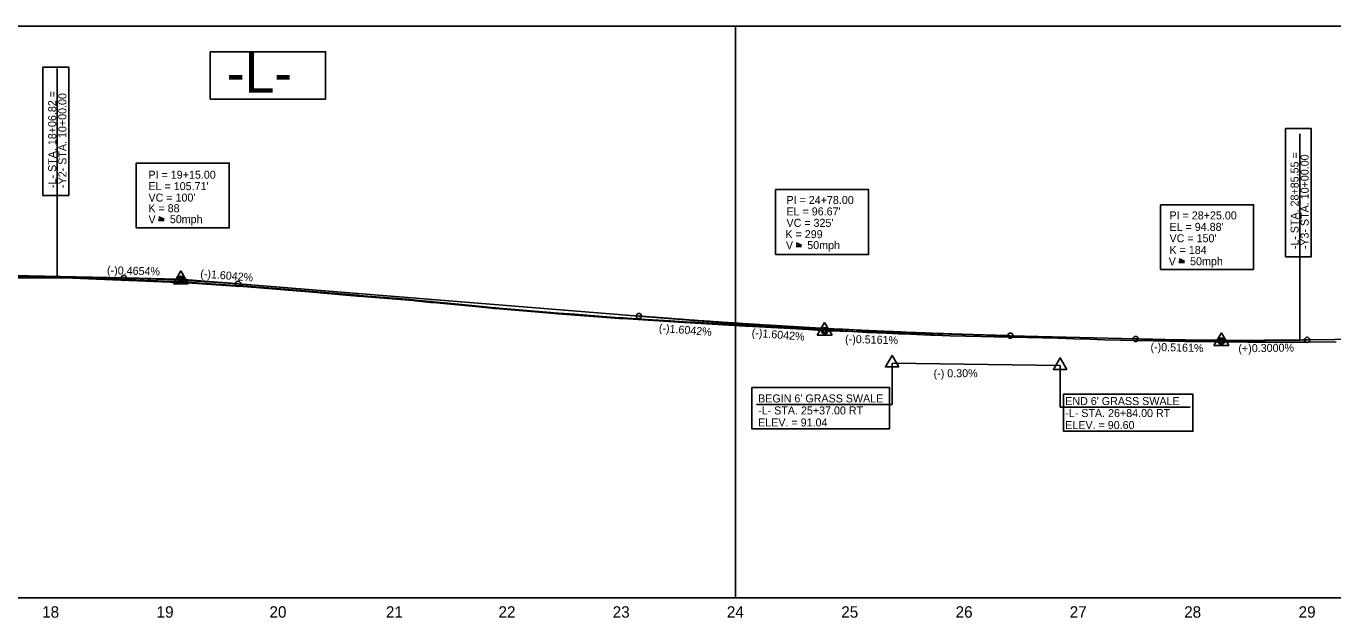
# Model space of a CAD drawing. Extents: x 2366464 to 2375718, y 801842 to 804354.
# Drawn here: x 2368098 to 2369240, y 803836 to 804354 of the extents above; entities that cross this region are included whole.
import ezdxf

# ---------------------------------------------------------------- set-up
doc = ezdxf.new("R2010")
doc.units = 0
for name, color, linetype in [('Exist Profile Cell', 7, 'Continuous'), ('Exist Vertical Profile Ground Line', 7, 'Continuous'), ('Exist Vertical Profile Horizontal Axis Label Major', 7, 'Continuous'), ('Prop Grid Mask', 7, 'Continuous'), ('Prop PFL VPI Symbol CELL', 7, 'Continuous'), ('Prop Vertical Profile Curve Label', 7, 'Continuous'), ('Prop Vertical Profile Ditch Grade Right', 7, 'Continuous'), ('Prop Vertical Profile Ditch Grade Right Label', 7, 'Continuous'), ('Prop Vertical Profile Grade', 7, 'Continuous'), ('Prop Vertical Profile Grade Label', 7, 'Continuous'), ('Prop VPI Label', 7, 'Continuous'), ('Scratch_Level_5', 7, 'Continuous'), ('Sheet Layout Profile Border Port 1', 7, 'Continuous'), ('Sheet Layout Profile Border Port 2', 7, 'Continuous')]:
    doc.layers.add(name, color=color, linetype=linetype)

# ---------------------------------------------------------------- blocks, each defined once
blk = doc.blocks.new('Profile VPI Symbol')
at = {"layer": 'Prop PFL VPI Symbol CELL'}
for p, q in [((-0.001, 0.147), (-0.13, -0.077)), ((-0.001, 0.147), (0.129, -0.077)), ((-0.13, -0.077), (0.129, -0.077))]:
    blk.add_line(p, q, dxfattribs=at)
for radius in [0.035, 0.024]:
    blk.add_circle((-0.001, -0.003), radius, dxfattribs=at)

msp = doc.modelspace()

# ---------------------------------------------------------------- linework, layer by layer
at = {"layer": 'Exist Profile Cell'}
msp.add_line((2367318, 803854), (2374481.8, 803854), dxfattribs=at)
at = {"layer": 'Exist Vertical Profile Ground Line'}
for points in [[(2368089.7, 804134.6), (2368138.2, 804134.2), (2368187.3, 804132.2), (2368187.8, 804132.2), (2368237.8, 804130), (2368238.2, 804130), (2368238.5, 804129.9), (2368280.6, 804127.2), (2368287.8, 804126.8), (2368337.8, 804122.6), (2368338.4, 804122.6), (2368387.6, 804118.5), (2368388.5, 804118.4), (2368430.6, 804115), (2368436.1, 804114.5), (2368438.1, 804114.3), (2368451.5, 804113), (2368452.1, 804113), (2368452.9, 804112.9), (2368453.8, 804112.8), (2368472.5, 804111), (2368493.5, 804108.9), (2368507.2, 804107.6), (2368507.6, 804107.5), (2368508.1, 804107.5), (2368514.5, 804107), (2368535.4, 804105.3), (2368556.4, 804103.5), (2368562.6, 804103), (2368563.1, 804103), (2368577.4, 804101.9), (2368598.4, 804100.3), (2368616.3, 804098.9), (2368618.5, 804098.8), (2368619.4, 804098.7), (2368640.3, 804097.4), (2368661.3, 804096.1), (2368672.8, 804095.4), (2368673.4, 804095.4), (2368682.3, 804094.9), (2368703.2, 804093.6), (2368724.2, 804092.4), (2368726.7, 804092.3), (2368727.3, 804092.2), (2368727.7, 804092.2), (2368745.2, 804091.2), (2368766.1, 804090), (2368781.9, 804089.1), (2368787.1, 804088.8)], [(2368787.1, 804088.8), (2368802.9, 804087.9), (2368808.1, 804087.6), (2368829.1, 804086.4), (2368832.6, 804086.2), (2368833, 804086.1), (2368850, 804085.4), (2368860.4, 804084.9), (2368871, 804084.5), (2368888.6, 804083.7), (2368889.1, 804083.7), (2368892, 804083.6), (2368905.6, 804083.2), (2368919.1, 804082.9), (2368932.7, 804082.5), (2368944.4, 804082.2), (2368944.9, 804082.2), (2368946.2, 804082.2), (2368959.8, 804081.8), (2368973.3, 804081.5), (2368986.9, 804081.2), (2368999.8, 804080.9), (2369000.5, 804080.9), (2369014, 804080.5), (2369027.6, 804080.1), (2369041.1, 804079.7), (2369054.7, 804079.3), (2369055.5, 804079.3), (2369068.2, 804079), (2369070.3, 804079), (2369111.4, 804078), (2369165.9, 804077.6), (2369203.5, 804077.6), (2369218.2, 804077.6), (2369218.7, 804077.6), (2369243.4, 804077.7)]]:
    msp.add_lwpolyline(points, dxfattribs=at)
at = {"layer": 'Prop Grid Mask'}
for points in [[(2368258.7, 804331.5), (2368359.5, 804331.5), (2368359.5, 804290.2), (2368258.7, 804290.2)], [(2368112.3, 804205.9), (2368112.3, 804318), (2368134.9, 804318), (2368134.9, 804205.9)], [(2369198.9, 804152.3), (2369198.9, 804264.4), (2369221.5, 804264.4), (2369221.5, 804152.3)], [(2368193.9, 804234.2), (2368275.2, 804234.2), (2368275.2, 804177.5), (2368193.9, 804177.5)], [(2368753.1, 804211), (2368834.4, 804211), (2368834.4, 804154.3), (2368753.1, 804154.3)], [(2369089.8, 804197.8), (2369171.2, 804197.8), (2369171.2, 804141.1), (2369089.8, 804141.1)], [(2368732.4, 804037.9), (2368852.7, 804037.9), (2368852.7, 804001.7), (2368732.4, 804001.7)], [(2369005, 804032), (2369118.1, 804032), (2369118.1, 803999.6), (2369005, 803999.6)]]:
    msp.add_lwpolyline(points, close=True, dxfattribs=at)
at = {"layer": 'Prop Vertical Profile Curve Label'}
for p, q in [((2368218.3, 804185.1), (2368213.6, 804187.1)), ((2368213.5, 804185.1), (2368218.3, 804185.1)), ((2368213.5, 804184), (2368218.3, 804184)), ((2368775.8, 804162.4), (2368771.2, 804164.4)), ((2368771.1, 804162.4), (2368775.8, 804162.4)), ((2368771.1, 804161.3), (2368775.8, 804161.3)), ((2369105.9, 804148.3), (2369110.6, 804148.3)), ((2369105.9, 804147.2), (2369110.6, 804147.2)), ((2369110.6, 804148.3), (2369106, 804150.3))]:
    msp.add_line(p, q, dxfattribs=at)
for centre in [(2368183, 804133.7), (2368283, 804128.5), (2368633.5, 804100.4), (2368958.5, 804083.2), (2369068, 804080.3), (2369218, 804079.5)]:
    msp.add_circle(centre, 2.25, dxfattribs=at)
at = {"layer": 'Prop Vertical Profile Ditch Grade Right'}
msp.add_line((2369002, 804057), (2368855, 804059.2), dxfattribs=at)
at = {"layer": 'Prop Vertical Profile Ditch Grade Right Label'}
for p, q in [((2368855, 804022.9), (2368855, 804059.2)), ((2369002, 804020.7), (2369002, 804057)), ((2368855, 804022.9), (2368736.5, 804022.9)), ((2369115.7, 804020.7), (2369002, 804020.7))]:
    msp.add_line(p, q, dxfattribs=at)
for points in [[(2368860.8, 804055.8), (2368855, 804065.9), (2368849.1, 804055.8)], [(2369007.8, 804053.6), (2369002, 804063.7), (2368996.1, 804053.6)]]:
    msp.add_lwpolyline(points, close=True, dxfattribs=at)
at = {"layer": 'Prop Vertical Profile Grade'}
for p, q in [((2367768, 804143.3), (2368183, 804133.7)), ((2368283, 804128.5), (2368633.5, 804100.4)), ((2368958.5, 804083.2), (2369068, 804080.3)), ((2369218, 804079.5), (2369269, 804080.3))]:
    msp.add_line(p, q, dxfattribs=at)
for points in [[(2368183, 804133.7), (2368185, 804133.6), (2368187, 804133.6), (2368189, 804133.5), (2368191, 804133.5), (2368193, 804133.4), (2368195, 804133.4), (2368197, 804133.3), (2368199, 804133.2), (2368201, 804133.2), (2368203, 804133.1), (2368205, 804133), (2368207, 804133), (2368209, 804132.9), (2368211, 804132.8), (2368213, 804132.7), (2368215, 804132.6), (2368217, 804132.6), (2368219, 804132.5), (2368221, 804132.4), (2368223, 804132.3), (2368225, 804132.2), (2368227, 804132.1), (2368229, 804132), (2368231, 804131.9), (2368233, 804131.8), (2368235, 804131.7), (2368237, 804131.6), (2368239, 804131.5), (2368241, 804131.4), (2368243, 804131.3), (2368245, 804131.1), (2368247, 804131), (2368249, 804130.9), (2368251, 804130.8), (2368253, 804130.7), (2368255, 804130.5), (2368257, 804130.4), (2368259, 804130.3), (2368261, 804130.1), (2368263, 804130), (2368265, 804129.9), (2368267, 804129.7), (2368269, 804129.6), (2368271, 804129.4), (2368273, 804129.3), (2368275, 804129.1), (2368277, 804129), (2368279, 804128.8), (2368281, 804128.7), (2368283, 804128.5)], [(2368633.5, 804100.4), (2368640, 804099.9), (2368646.5, 804099.4), (2368653, 804098.9), (2368659.5, 804098.4), (2368666, 804097.9), (2368672.5, 804097.4), (2368679, 804096.9), (2368685.5, 804096.4), (2368692, 804096), (2368698.5, 804095.5), (2368705, 804095.1), (2368711.5, 804094.6), (2368718, 804094.2), (2368724.5, 804093.8), (2368731, 804093.4), (2368737.5, 804093), (2368744, 804092.5), (2368750.5, 804092.2), (2368757, 804091.8), (2368763.5, 804091.4), (2368770, 804091), (2368776.5, 804090.6), (2368783, 804090.3), (2368789.5, 804089.9), (2368796, 804089.6), (2368802.5, 804089.2), (2368809, 804088.9), (2368815.5, 804088.6), (2368822, 804088.2), (2368828.5, 804087.9), (2368835, 804087.6), (2368841.5, 804087.3), (2368848, 804087), (2368854.5, 804086.8), (2368861, 804086.5), (2368867.5, 804086.2), (2368874, 804085.9), (2368880.5, 804085.7), (2368887, 804085.4), (2368893.5, 804085.2), (2368900, 804085), (2368906.5, 804084.7), (2368913, 804084.5), (2368919.5, 804084.3), (2368926, 804084.1), (2368932.5, 804083.9), (2368939, 804083.7), (2368945.5, 804083.5), (2368952, 804083.3), (2368958.5, 804083.2)], [(2369068, 804080.3), (2369071, 804080.3), (2369074, 804080.2), (2369077, 804080.1), (2369080, 804080), (2369083, 804080), (2369086, 804079.9), (2369089, 804079.9), (2369092, 804079.8), (2369095, 804079.7), (2369098, 804079.7), (2369101, 804079.6), (2369104, 804079.6), (2369107, 804079.5), (2369110, 804079.5), (2369113, 804079.4), (2369116, 804079.4), (2369119, 804079.4), (2369122, 804079.3), (2369125, 804079.3), (2369128, 804079.3), (2369131, 804079.2), (2369134, 804079.2), (2369137, 804079.2), (2369140, 804079.2), (2369143, 804079.2), (2369146, 804079.2), (2369149, 804079.1), (2369152, 804079.1), (2369155, 804079.1), (2369158, 804079.1), (2369161, 804079.1), (2369164, 804079.1), (2369167, 804079.1), (2369170, 804079.1), (2369173, 804079.1), (2369176, 804079.1), (2369179, 804079.1), (2369182, 804079.2), (2369185, 804079.2), (2369188, 804079.2), (2369191, 804079.2), (2369194, 804079.2), (2369197, 804079.3), (2369200, 804079.3), (2369203, 804079.3), (2369206, 804079.4), (2369209, 804079.4), (2369212, 804079.4), (2369215, 804079.5), (2369218, 804079.5)]]:
    msp.add_spline(points, degree=3, dxfattribs=at)
at = {"layer": 'Prop VPI Label'}
for p, q in [((2368124.8, 804135), (2368124.8, 804317)), ((2369211.5, 804079.4), (2369211.5, 804259.8)), ((2368183, 804133.7), (2368230.2, 804132.6)), ((2368283, 804128.5), (2368235.7, 804132.3)), ((2368633.5, 804100.4), (2368793.2, 804087.6)), ((2368958.5, 804083.2), (2368798.7, 804087.3)), ((2369068, 804080.3), (2369140.2, 804078.5)), ((2369218, 804079.5), (2369145.7, 804078.4))]:
    msp.add_line(p, q, dxfattribs=at)
for centre in [(2368233, 804132.5), (2368796, 804087.4), (2369143, 804078.4)]:
    msp.add_circle(centre, 2.75, dxfattribs=at)
at = {"layer": 'Scratch_Level_5'}
for p, q in [((2368118, 804135.1), (2368118, 804135.1)), ((2368468, 804112.7), (2368468, 804112.7)), ((2368568, 804104.1), (2368568, 804104.1)), ((2368768, 804091.1), (2368768, 804091.1)), ((2369168, 804079), (2369168, 804079)), ((2369211, 804079), (2369211, 804079))]:
    msp.add_line(p, q, dxfattribs=at)
msp.add_lwpolyline([(2368089.7, 804133.9), (2368138.2, 804133.6), (2368187.3, 804131.6), (2368187.8, 804131.6), (2368237.8, 804129.4), (2368238.1, 804129.3), (2368238.5, 804129.3), (2368280.6, 804126.6), (2368287.7, 804126.2), (2368337.7, 804122), (2368338.4, 804122), (2368387.5, 804117.9), (2368388.4, 804117.8), (2368436.1, 804113.9), (2368438.1, 804113.7), (2368451.5, 804112.3), (2368452.1, 804112.3), (2368452.9, 804112.3), (2368453.7, 804112.2), (2368493.4, 804108.3), (2368507.2, 804106.9), (2368507.5, 804106.9), (2368508.1, 804106.9), (2368556.4, 804102.9), (2368562.5, 804102.4), (2368563, 804102.4), (2368616.3, 804098.3), (2368618.4, 804098.1), (2368619.4, 804098.1), (2368672.8, 804094.8), (2368673.4, 804094.7), (2368726.7, 804091.6), (2368727.3, 804091.6), (2368727.6, 804091.6), (2368766.1, 804089.4), (2368781.8, 804088.5), (2368787.1, 804088.2)], dxfattribs=at)
at = {"layer": 'Sheet Layout Profile Border Port 1'}
msp.add_lwpolyline([(2367318, 803854), (2368718, 803854), (2368718, 804354), (2367318, 804354)], close=True, dxfattribs=at)
at = {"layer": 'Sheet Layout Profile Border Port 2'}
msp.add_lwpolyline([(2368718, 803854), (2370118, 803854), (2370118, 804354), (2368718, 804354)], close=True, dxfattribs=at)

# ---------------------------------------------------------------- block references
at = {"layer": 'Prop Grid Mask', "xscale": 50, "yscale": 50}
for p in [(2368233, 804132.5), (2368796, 804087.4), (2369143, 804078.4)]:
    msp.add_blockref('Profile VPI Symbol', p, dxfattribs=at)

# ---------------------------------------------------------------- texts
at = {"layer": 'Exist Vertical Profile Horizontal Axis Label Major'}
for s, p in [('18', (2368111.6, 803836.5)), ('19', (2368211.7, 803836.5)), ('20', (2368310.4, 803836.5)), ('21', (2368412.2, 803836.5)), ('22', (2368510.7, 803836.5)), ('23', (2368610.6, 803836.5)), ('24', (2368710.4, 803836.5)), ('25', (2368810.5, 803836.5)), ('26', (2368910.5, 803836.5)), ('27', (2369010.3, 803836.5)), ('28', (2369110.4, 803836.5)), ('29', (2369210.5, 803836.5))]:
    msp.add_text(s, height=10, dxfattribs=at).set_placement(p)
at = {"layer": 'Prop Vertical Profile Curve Label'}
for s, p in [('-L- STA. 18+06.82 = ', (2368123.9, 804212.4)), ('-Y2- STA. 10+00.00', (2368132.8, 804212.4)), ('-L- STA. 28+85.55 = ', (2369210.5, 804158.8)), ('-Y3- STA. 10+00.00', (2369219.3, 804158.8))]:
    msp.add_text(s, height=7, rotation=90, dxfattribs=at).set_placement(p)
for s, p in [("VC = 100'", (2368204.6, 804200.5)), ('K = 88', (2368204.5, 804191.2)), ('V', (2368204.6, 804181.5)), ('50mph', (2368223.3, 804181.6)), ('K = 299', (2368761.7, 804168.5)), ("VC = 325'", (2368762.6, 804178.4)), ('V', (2368762.1, 804158.8)), ('50mph', (2368780.8, 804158.9)), ("VC = 150'", (2369097.6, 804164.9)), ('V', (2369096.9, 804144.7)), ('K = 184', (2369097.6, 804154.7)), ('50mph', (2369115.6, 804144.8))]:
    msp.add_text(s, height=7, dxfattribs=at).set_placement(p)
at = {"layer": 'Prop Vertical Profile Ditch Grade Right Label'}
msp.add_text('(-) 0.30%', height=7, rotation=0.3614, dxfattribs=at).set_placement((2368891.3, 804046.7))
for s, p in [("BEGIN 6' GRASS SWALE", (2368737.8, 804024.8)), ("END 6' GRASS SWALE", (2369006.4, 804022.5)), ('-L- STA. 25+37.00 RT', (2368737.8, 804014.3)), ('-L- STA. 26+84.00 RT', (2369006.4, 804012)), ('ELEV. = 91.04', (2368737.8, 804003.8)), ('ELEV. = 90.60', (2369006.4, 804001.5))]:
    msp.add_text(s, height=7, dxfattribs=at).set_placement(p)
at = {"layer": 'Prop Vertical Profile Grade Label'}
for s, rotation, p in [('(-)0.4654%', 358.6668, (2368168.3, 804137)), ('(-)1.6042%', 355.4141, (2368249.7, 804134.2)), ('(-)1.6042%', 355.4141, (2368650.8, 804086.6)), ('(-)1.6042%', 355.4141, (2368732, 804082.5)), ('(-)0.5161%', 358.5217, (2368813.8, 804076.9)), ('(-)0.5161%', 358.5217, (2369080.9, 804070)), ('(+)0.3000%', 0.8594, (2369157.9, 804068.6))]:
    msp.add_text(s, height=7, rotation=rotation, dxfattribs=at).set_placement(p)
at = {"layer": 'Prop VPI Label'}
for s, height, p in [('-L-', 35, (2368273.1, 804295.7)), ('PI = 19+15.00', 7, (2368204.6, 804220.5)), ("EL = 105.71'", 7, (2368204.6, 804210.5)), ('PI = 24+78.00', 7, (2368762.6, 804198.4)), ("EL = 96.67'", 7, (2368762.6, 804188.4)), ('PI = 28+25.00', 7, (2369097.6, 804184.9)), ("EL = 94.88'", 7, (2369097.6, 804174.9))]:
    msp.add_text(s, height=height, dxfattribs=at).set_placement(p)

doc.saveas('drawing.dxf')
